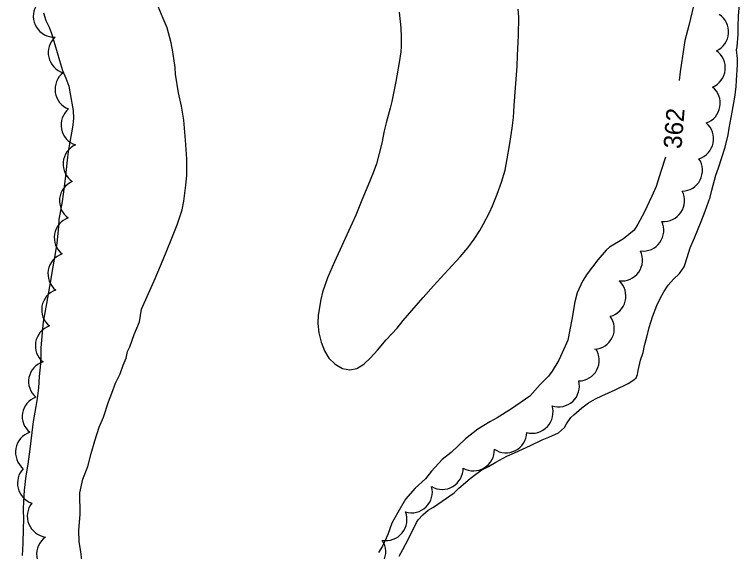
# Model space of a CAD drawing. Extents: x 287698 to 290158, y 5234163 to 5237182.
# Drawn here: x 288600.4 to 288720.4, y 5235484.4 to 5235573.3 of the extents above; entities that cross this region are included whole.
import ezdxf

# ---------------------------------------------------------------- set-up
doc = ezdxf.new("R2010")
doc.units = 0
for name, color, linetype in [('Niveau 2', 7, 'Continuous'), ('Niveau 4', 7, 'Continuous'), ('Niveau 44', 7, 'Continuous')]:
    doc.layers.add(name, color=color, linetype=linetype)

msp = doc.modelspace()

# ---------------------------------------------------------------- linework, layer by layer
at = {"layer": 'Niveau 2'}
for points in [[(288611.52, 5235482.97), (288611.39, 5235484.4), (288611.08, 5235486), (288611.04, 5235487.9), (288611.27, 5235490.48), (288611.2, 5235494.09), (288611.73, 5235496.38), (288612.55, 5235498.48), (288613.08, 5235500.59), (288613.7, 5235502.69), (288614.42, 5235504.97), (288615.15, 5235506.61), (288615.96, 5235509.18), (288616.5, 5235510.62), (288617.14, 5235512.25), (288617.87, 5235513.78), (288618.41, 5235515.22), (288618.86, 5235516.37), (288619.13, 5235517.52), (288619.49, 5235518.28), (288620.21, 5235520.29), (288621.12, 5235522.4), (288621.42, 5235524.48), (288622.6, 5235527.1), (288623.7, 5235529.6), (288625.03, 5235532.74), (288626.33, 5235536), (288627.32, 5235538.48), (288628.13, 5235540.94), (288628.44, 5235542.41), (288628.79, 5235545.01), (288628.91, 5235546.64), (288628.93, 5235549.4), (288628.69, 5235552.48), (288628.41, 5235555.78), (288628.06, 5235558.14), (288627.53, 5235560.32), (288627.07, 5235563.43), (288627.01, 5235564.49), (288626.63, 5235567.12), (288626.32, 5235568.59), (288625.65, 5235571.06), (288624.99, 5235572.63), (288623.88, 5235575.3)], [(288712.88, 5235574.95), (288712.04, 5235571.48), (288711.37, 5235568.96), (288711.2, 5235567.88), (288710.64, 5235563.8), (288710.46, 5235562.34)], [(288664.09, 5235573.67), (288664.39, 5235571.06), (288664.44, 5235569.6), (288664.44, 5235567.99), (288664.35, 5235567.1), (288664.07, 5235565.36), (288663.51, 5235562.21), (288662.9, 5235558.86), (288662.61, 5235557.78), (288661.92, 5235555.38), (288661.61, 5235554.03), (288661.2, 5235552.01), (288660.78, 5235550.27), (288660.31, 5235548.59), (288659.79, 5235547.09), (288658.91, 5235544.94), (288657.93, 5235542.55), (288656.9, 5235540.04), (288656.28, 5235538.73), (288654.85, 5235535.59), (288653.37, 5235532.32), (288652.21, 5235529.7), (288651.37, 5235527.34), (288651.12, 5235526.09), (288650.69, 5235523.51), (288650.63, 5235522.12), (288650.79, 5235520.61), (288651.15, 5235519.04), (288651.7, 5235517.63), (288652.44, 5235516.41), (288653.47, 5235515.37), (288654.69, 5235514.7), (288655.91, 5235514.47), (288657.07, 5235514.69), (288658.21, 5235515.4), (288659.33, 5235516.47), (288660.48, 5235517.72), (288661.96, 5235519.4), (288663.74, 5235521.37), (288664.75, 5235522.6), (288666.88, 5235525.13), (288668.04, 5235526.42), (288669.76, 5235528.36), (288672.2, 5235531.01), (288674.2, 5235533.18), (288675.46, 5235534.67), (288676.52, 5235536.08), (288677.45, 5235537.52), (288678, 5235538.52), (288679.03, 5235540.5), (288679.53, 5235541.61), (288680.32, 5235543.54), (288681.03, 5235545.54), (288681.62, 5235547.54), (288681.98, 5235549.4), (288682.37, 5235551.61), (288682.82, 5235554.48), (288683.02, 5235556.21), (288683.15, 5235558.21), (288683.35, 5235561.15), (288683.61, 5235564.72), (288683.69, 5235566.5), (288683.83, 5235569.8), (288683.88, 5235572.9), (288683.8, 5235574.18)], [(288708.17, 5235549.69), (288707.42, 5235547.3), (288706.62, 5235544.79), (288705.93, 5235543.2), (288704.64, 5235540.5), (288703.63, 5235538.59), (288703.02, 5235537.61), (288701.24, 5235536.15), (288698.92, 5235534.75), (288698.35, 5235534.26), (288696.99, 5235532.68), (288695.21, 5235530.35), (288694.46, 5235529.16), (288693.54, 5235527.21), (288693.15, 5235525.7), (288692.69, 5235522.77), (288692.02, 5235519.36), (288691.58, 5235518.36), (288690.5, 5235516.05), (288689.44, 5235514.21), (288688.83, 5235513.42), (288687.42, 5235512.02)], [(288687.42, 5235512.02), (288685.71, 5235510.12), (288682.67, 5235508), (288680.31, 5235506.53), (288679.09, 5235505.84), (288677.12, 5235504.66), (288675.05, 5235503.01), (288672.72, 5235500.78), (288671.22, 5235499.61), (288669.45, 5235497.68), (288668.43, 5235496.42), (288666.75, 5235494.87), (288665.16, 5235493.03), (288663.87, 5235490.82), (288662.86, 5235489.09), (288662.23, 5235487.18), (288661.32, 5235485.26), (288660.67, 5235484.21)]]:
    msp.add_lwpolyline(points, dxfattribs=at)
at = {"layer": 'Niveau 4'}
for points in [[(288664.07, 5235483.63), (288664.69, 5235484.69), (288665.64, 5235486.47), (288666.95, 5235489.16), (288667.22, 5235489.63), (288667.99, 5235490.46), (288668.88, 5235491.21), (288669.76, 5235491.73), (288671.2, 5235492.7), (288673.18, 5235494.09), (288673.99, 5235494.85), (288675.82, 5235496.46), (288676.76, 5235497.2), (288677.8, 5235497.9), (288678.9, 5235498.48), (288680.08, 5235499.17), (288681.93, 5235500.15), (288683.16, 5235500.71), (288685.82, 5235501.94), (288687.74, 5235502.87), (288688.85, 5235503.29), (288690.49, 5235504.04), (288691.44, 5235504.91), (288691.78, 5235505.52), (288692.49, 5235506.55), (288692.99, 5235507.01), (288694.36, 5235508.15), (288695.46, 5235508.98), (288696.59, 5235509.68), (288697.64, 5235510.17), (288699.86, 5235511.14), (288702.03, 5235512.2), (288702.97, 5235512.79), (288703.34, 5235513.15), (288703.53, 5235513.67), (288703.65, 5235514.34), (288704.05, 5235516.05), (288704.47, 5235517.32), (288704.71, 5235518.49), (288705.1, 5235519.84), (288705.51, 5235521.49), (288706.03, 5235523.24), (288706.73, 5235525.12), (288707.28, 5235526.26), (288707.93, 5235527.38), (288708.64, 5235528.45), (288709.52, 5235529.47), (288710.51, 5235530.41), (288711.27, 5235531.53), (288711.49, 5235532.18), (288712.28, 5235534.65), (288713.01, 5235536.31), (288714.11, 5235538.99), (288714.76, 5235540.74), (288715.57, 5235543.06), (288715.86, 5235544.22), (288716.5, 5235546.7), (288716.95, 5235547.89), (288717.54, 5235549.64), (288718.05, 5235551.34), (288718.55, 5235553.36), (288718.75, 5235554.49), (288719.21, 5235557.1), (288719.65, 5235559.58), (288719.88, 5235561.32), (288719.95, 5235562.41), (288720.11, 5235564.95), (288720.09, 5235565.99), (288719.95, 5235567.44), (288720.03, 5235567.94), (288720.24, 5235570.04), (288720.24, 5235571.19), (288720.3, 5235573.09), (288720.44, 5235575.01)], [(288605.17, 5235573.55), (288605.59, 5235572.29), (288606.15, 5235571.18), (288606.51, 5235570.12), (288607.07, 5235568.3), (288607.82, 5235565.7), (288608.36, 5235564.02), (288608.92, 5235562.73), (288609.38, 5235561.4), (288609.64, 5235560.13), (288610.13, 5235557.42), (288610.19, 5235556.11), (288610.07, 5235554.99), (288609.84, 5235553.72), (288609.29, 5235550.6), (288609.11, 5235549.15), (288608.78, 5235546.1), (288608.48, 5235543.55), (288608.27, 5235542.33), (288607.76, 5235539.35), (288607.68, 5235538.16), (288607.43, 5235535.42), (288607.19, 5235534.07), (288606.74, 5235531.51), (288606.17, 5235528.28), (288605.67, 5235525.45), (288605.13, 5235522.4), (288605.01, 5235521.23), (288604.78, 5235518.09), (288604.78, 5235516.84), (288604.68, 5235515.46), (288604.48, 5235513.38), (288604.37, 5235511.47), (288604.17, 5235509.71), (288603.94, 5235508.41), (288603.5, 5235505.88), (288603.26, 5235504.08), (288602.91, 5235501.32), (288602.59, 5235498.84), (288602.29, 5235496.91), (288602.02, 5235494.55), (288601.87, 5235492.67), (288601.84, 5235491.42), (288601.87, 5235489.57), (288601.83, 5235488.2), (288601.8, 5235485.68), (288601.69, 5235483.73)]]:
    msp.add_lwpolyline(points, dxfattribs=at)
at = {"layer": 'Niveau 44'}
for centre, radius, start, end in [((288606.97, 5235573), 3.46, 150.4392, 272.5901), ((288611.3, 5235542.43), 3.46, 112.5859, 234.7128), ((288698.16, 5235526.67), 3.47, 284.8886, 46.6259), ((288676.4, 5235501.18), 3.45, 240.137, 2.1816), ((288671.22, 5235498.12), 3.46, 239.6246, 1.2296), ((288606.01, 5235490.24), 3.5, 142.1883, 261.9673), ((288607.56, 5235483.93), 3.5, 125.5746, 247.5606)]:
    msp.add_arc(centre, radius, start, end, dxfattribs=at)
for centre, major_axis, ratio, start_param, end_param in [((288715.18, 5235570.41), (3.38, -0.69), 0.999764, 5.346258, 7.474754), ((288609.43, 5235566.96), (-3.43, 0.36), 0.999962, 5.543632, 7.673846), ((288714.63, 5235564.46), (3.44, -0.37), 0.999336, 5.223803, 7.345113), ((288610.58, 5235560.9), (2.17, -2.71), 0.999995, 3.120245, 5.242747), ((288713.81, 5235558.6), (3.4, -0.6), 0.999951, 5.221534, 7.346548), ((288611.57, 5235555), (-3.4, -0.67), 0.999995, 5.217278, 7.344884), ((288712.68, 5235552.71), (3.4, -0.7), 0.99956, 5.218909, 7.348089), ((288611.92, 5235548.52), (1.5, -3.15), 0.999995, 3.117361, 5.243901), ((288710.85, 5235547.48), (2.93, -1.83), 0.999392, 5.30137, 7.429187), ((288707.87, 5235542.47), (2.09, -2.76), 0.999962, 5.550469, 7.674921), ((288610.46, 5235536.34), (-3.4, 0.72), 0.99813, 5.264303, 7.383446), ((288704.44, 5235537.57), (2.74, -2.12), 0.99746, 5.258432, 7.376392), ((288609.41, 5235530.37), (-3.37, 0.84), 0.999278, 5.288452, 7.416919), ((288700.93, 5235532.64), (2.26, -2.63), 0.999929, 5.46074, 7.58786), ((288608.36, 5235524.41), (-3.38, 0.77), 0.998687, 5.270265, 7.395377), ((288696.29, 5235521.29), (1.47, 3.09), 0.999939, 3.634442, 5.790336), ((288607.31, 5235518.45), (-3.38, 0.77), 0.998687, 5.270265, 7.395377), ((288693.79, 5235516.04), (1.6, 3.03), 0.999861, 3.635426, 5.789352), ((288606.21, 5235512.49), (-3.41, 0.73), 0.985124, 5.238095, 7.342604), ((288690.51, 5235511.76), (1.92, -2.84), 0.997155, 5.357019, 7.511995), ((288605.18, 5235506.72), (-3.47, 0.56), 0.96979, 5.236367, 7.314813), ((288686.07, 5235507.45), (-1.04, 3.34), 0.999984, 2.595024, 4.721045), ((288604.07, 5235500.81), (-3.45, 0.62), 0.999567, 5.221539, 7.347521), ((288681.77, 5235504.18), (1.57, -3.08), 0.999951, 5.218447, 7.348101), ((288604.39, 5235495.69), (-3.34, -1.05), 0.999567, 5.221539, 7.220202), ((288666.13, 5235494.23), (2.4, -2.48), 0.999995, 5.222216, 7.347923), ((288661.91, 5235489.65), (2.69, -2.19), 0.999733, 5.218991, 7.343128), ((288658.39, 5235484.33), (3.02, -1.73), 0.997942, 5.257141, 7.382818)]:
    msp.add_ellipse(centre, major_axis=major_axis, ratio=ratio, start_param=start_param, end_param=end_param, dxfattribs=at)

# ---------------------------------------------------------------- texts
at = {"layer": 'Niveau 2'}
msp.add_text('362', height=3, rotation=85.2905, dxfattribs=at).set_placement((288710.82, 5235550.97))

doc.saveas('drawing.dxf')
